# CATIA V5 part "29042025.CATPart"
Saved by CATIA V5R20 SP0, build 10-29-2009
Part number: 29042025
Definition: NONE
Nomenclature: 29042025
Source: Unknown
Description: 29042025
Bounding box of the stored display mesh (mm): x -12.5 to 44.548, y -35 to 69.548, z -25 to 25
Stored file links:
  C:\Users\Utente\Desktop\IO LAVORO\3D X SITO CF\X SITO\PLASTICA\RF1\29042025.CATPart
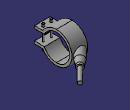
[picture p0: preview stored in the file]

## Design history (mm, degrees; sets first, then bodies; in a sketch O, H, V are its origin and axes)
Body1 "29042025" (main body)
  Solid1: solid without history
